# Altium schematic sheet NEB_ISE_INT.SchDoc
size A4; CompanyName: Altium; DrawnBy: Ch.W.; Organization: Altium Limited; Address1: L3, 12a Rodborough Rd; Address2: Frenchs Forest; Address3: NSW; Address4: Australia 2086; DocumentNumber: 5; Revision: V0.9; SheetNumber: 5; SheetTotal: 10
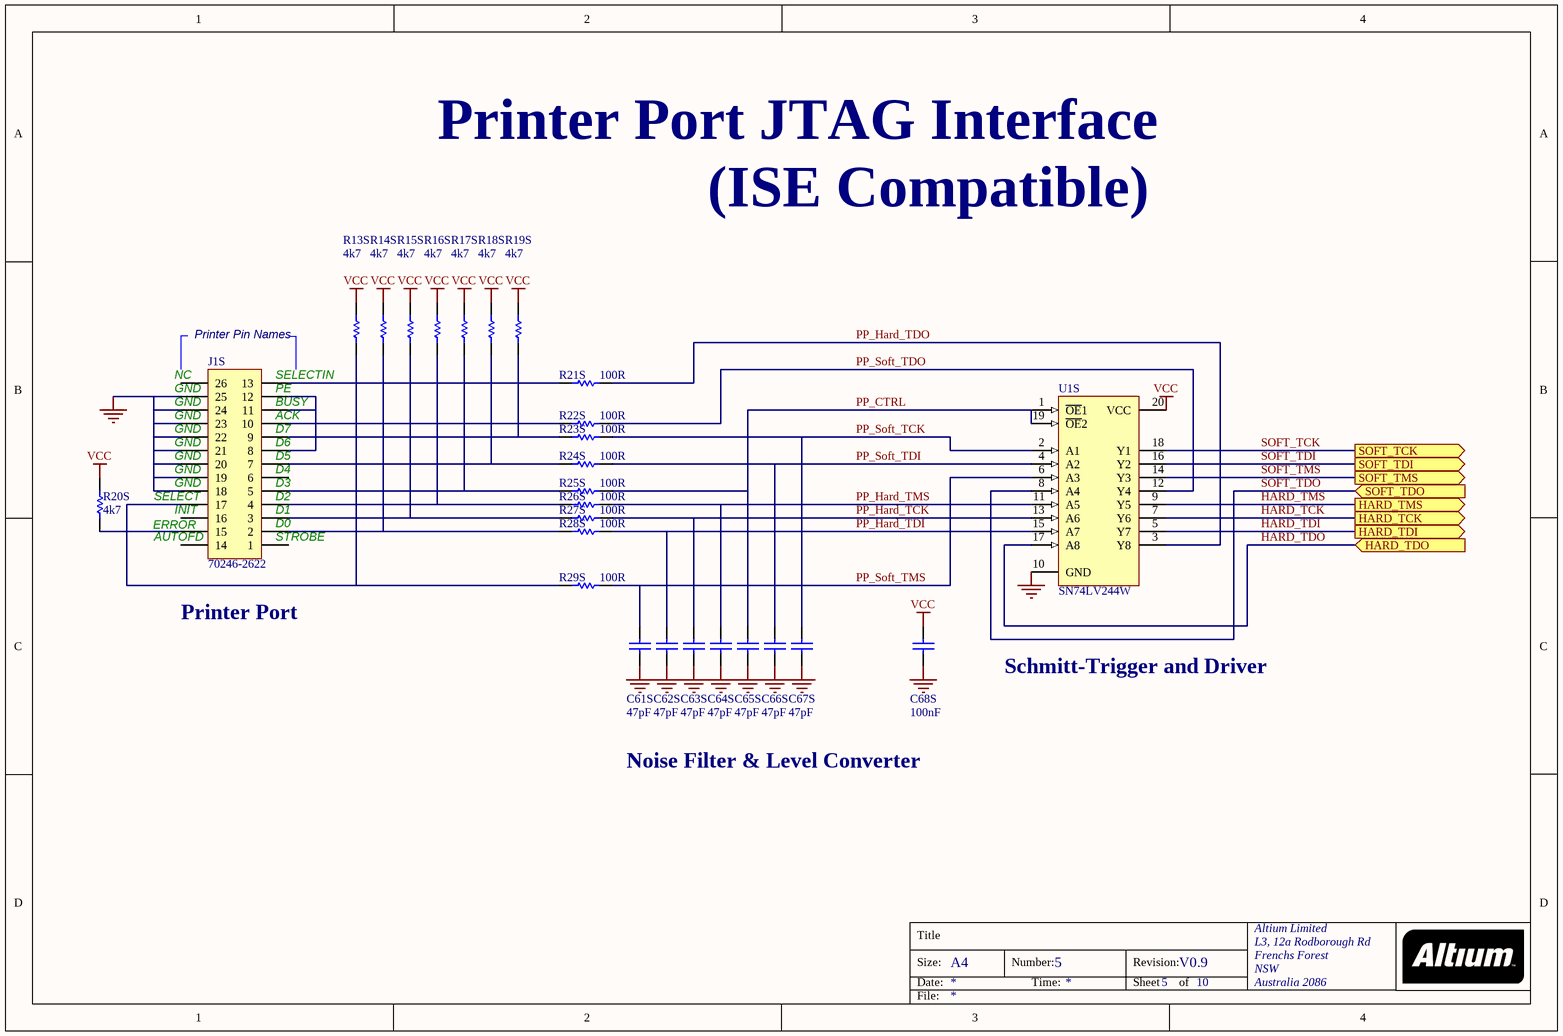
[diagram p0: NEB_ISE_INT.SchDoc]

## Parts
C61S  47pF  [CC2012-0805]
C62S  47pF  [CC2012-0805]
C63S  47pF  [CC2012-0805]
C64S  47pF  [CC2012-0805]
C65S  47pF  [CC2012-0805]
C66S  47pF  [CC2012-0805]
C67S  47pF  [CC2012-0805]
C68S  100nF  [CC2012-0805]
J1S  70246-2622  [HDR2X13_CEN_LP]
R13S  4k7  [CR2012-0805]
R14S  4k7  [CR2012-0805]
R15S  4k7  [CR2012-0805]
R16S  4k7  [CR2012-0805]
R17S  4k7  [CR2012-0805]
R18S  4k7  [CR2012-0805]
R19S  4k7  [CR2012-0805]
R20S  4k7  [CR2012-0805]
R21S  100R  [CR2012-0805]
R22S  100R  [CR2012-0805]
R23S  100R  [CR2012-0805]
R24S  100R  [CR2012-0805]
R25S  100R  [CR2012-0805]
R26S  100R  [CR2012-0805]
R27S  100R  [CR2012-0805]
R28S  100R  [CR2012-0805]
R29S  100R  [CR2012-0805]
U1S  SN74LV244W  [SSO-G20/P.65]

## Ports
HARD_TCK (out), HARD_TDI (out), HARD_TDO (in), HARD_TMS (out), SOFT_TCK (out), SOFT_TDI (out), SOFT_TDO (in), SOFT_TMS (out)

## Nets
GND: C61S.2 C62S.2 C63S.2 C64S.2 C65S.2 C66S.2 C67S.2 C68S.2 J1S.18 J1S.19 J1S.20 J1S.21 J1S.22 J1S.23 J1S.24 J1S.25 U1S.10(GND)
VCC: C68S.1 R13S.1 R14S.1 R15S.1 R16S.1 R17S.1 R18S.1 R19S.1 R20S.1 U1S.20(VCC)
HARD_TCK: U1S.7(Y6) ; port HARD_TCK
HARD_TDI: U1S.5(Y7) ; port HARD_TDI
HARD_TDO: U1S.17(A8) ; port HARD_TDO
HARD_TMS: U1S.9(Y5) ; port HARD_TMS
PP_CTRL: C65S.1 R25S.1 U1S.1(~{OE}1) U1S.19(~{OE}2)
PP_Hard_TCK: C63S.1 R27S.1 U1S.13(A6)
PP_Hard_TDI: C62S.1 R28S.1 U1S.15(A7)
PP_Hard_TDO: R21S.1 U1S.3(Y8)
PP_Hard_TMS: C64S.1 R26S.1 U1S.11(A5)
PP_Soft_TCK: C67S.1 R23S.1 U1S.2(A1)
PP_Soft_TDI: C66S.1 R24S.1 U1S.4(A2)
PP_Soft_TDO: R22S.1 U1S.12(Y4)
PP_Soft_TMS: C61S.1 R29S.1 U1S.6(A3)
SOFT_TCK: U1S.18(Y1) ; port SOFT_TCK
SOFT_TDI: U1S.16(Y2) ; port SOFT_TDI
SOFT_TDO: U1S.8(A4) ; port SOFT_TDO
SOFT_TMS: U1S.14(Y3) ; port SOFT_TMS
NetJ1S_2: J1S.2 R14S.2 R28S.2
NetJ1S_3: J1S.3 R15S.2 R27S.2
NetJ1S_4: J1S.4 R16S.2 R26S.2
NetJ1S_5: J1S.5 R17S.2 R25S.2
NetJ1S_7: J1S.7 R18S.2 R24S.2
NetJ1S_8: J1S.8 J1S.11 J1S.12
NetJ1S_9: J1S.9 R19S.2 R23S.2
NetJ1S_10: J1S.10 R22S.2
NetJ1S_13: J1S.13 R21S.2
NetJ1S_15: J1S.15 R20S.2
NetJ1S_17: J1S.17 R13S.2 R29S.2

Not connected (* = marked no-connect by the designer): J1S 1 6 14 16 26

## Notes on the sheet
- Printer Port JTAG Interface
- (ISE Compatible)
- (near J1S) NC
- Printer Pin Names
- (near J1S) SELECTIN
- (near J1S) GND
- (near J1S) PE
- (near J1S) BUSY
- (near J1S) ACK
- (near J1S) D6
- (near J1S) D7
- (near J1S) SELECT
- (near J1S) INIT
- (near J1S) D1
- (near J1S) D2
- (near J1S) D3
- (near J1S) D4
- (near J1S) D5
- (near J1S) ERROR
- (near J1S) AUTOFD
- (near J1S) STROBE
- (near J1S) D0
- Printer Port
- Schmitt-Trigger and Driver
- Noise Filter & Level Converter

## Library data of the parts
C61S C62S C63S C64S C65S C66S C67S C68S = CAP: Capacitor; Fitted: True
J1S = Header 13X2A: Header, 13-Pin, Dual row; Manufacturer: Generic Components; Class I: Connector; Fitted: True
R13S R14S R15S R16S R17S R18S R19S R20S R21S R22S R23S R24S R25S R26S R27S R28S R29S = RES: Resistor; Fitted: True
U1S = SN54LV244W: Octal Buffer/Driver with 3-State Outputs; Package Information: Latest Revision: Jan-1995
